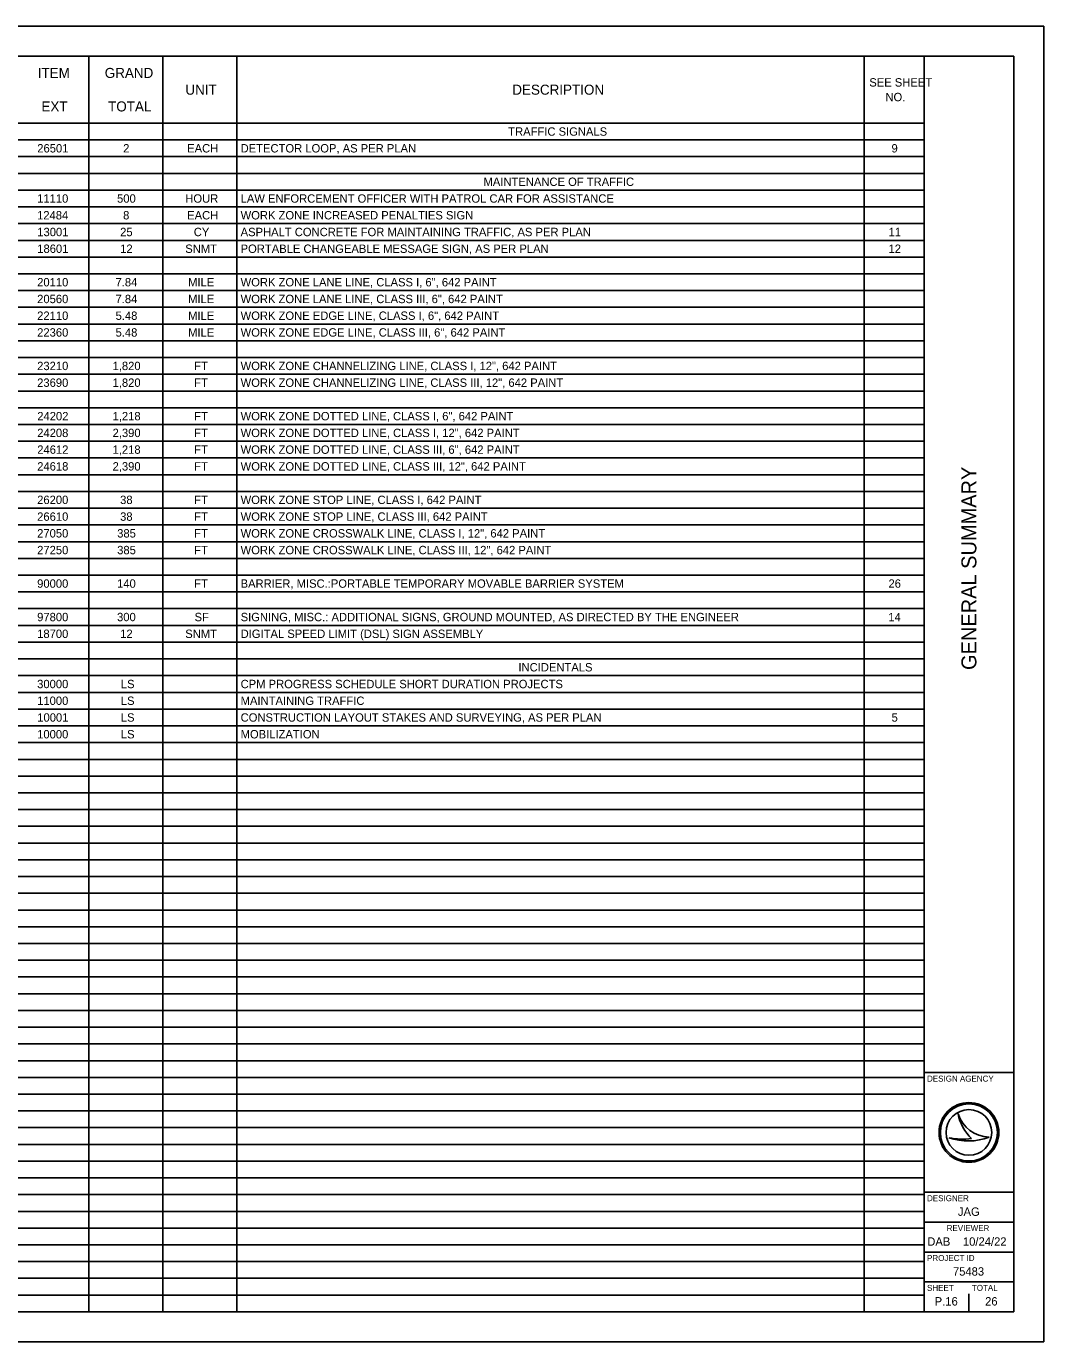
# Model space of a CAD drawing. Extents: x -32.2 to 34, y 0 to 22.
# Drawn here: x 16.99 to 34, y 0 to 22 of the extents above; entities that cross this region are included whole.
import ezdxf

# ---------------------------------------------------------------- set-up
doc = ezdxf.new("R2010")
doc.units = 0
for name, color, linetype in [('SH_Border', 7, 'Continuous'), ('SH_Cut_Line', 7, 'Continuous'), ('SH_Data', 7, 'Continuous'), ('SH_Text', 7, 'Continuous')]:
    doc.layers.add(name, color=color, linetype=linetype)

msp = doc.modelspace()

# ---------------------------------------------------------------- linework, layer by layer
at = {"layer": 'SH_Border'}
for p, q in [((32, 0.5), (32, 21.5)), ((32, 4.5), (33.5, 4.5)), ((32, 2.5), (33.5, 2.5)), ((32, 2), (33.5, 2)), ((32, 1.5), (33.5, 1.5)), ((32, 1), (33.5, 1))]:
    msp.add_line(p, q, dxfattribs=at)
msp.add_lwpolyline([(1.5, 21.5), (33.5, 21.5), (33.5, 0.5), (1.5, 0.5)], close=True, dxfattribs=at)
at = {"layer": 'SH_Cut_Line'}
msp.add_lwpolyline([(0, 0), (34, 0), (34, 22), (0, 22)], close=True, dxfattribs=at)
at = {"layer": 'SH_Data'}
for p, q in [((32.567, 3.81), (32.567, 3.81)), ((32.417, 3.41), (32.417, 3.41)), ((32.75, 3.5), (32.75, 3.5)), ((33.087, 3.419), (33.087, 3.419)), ((32.375, 0.675), (32.375, 0.675)), ((32.75, 0.5), (32.75, 0.8))]:
    msp.add_line(p, q, dxfattribs=at)
for radius in [0.5, 0.477, 0.477, 0.382]:
    msp.add_circle((32.75, 3.5), radius, dxfattribs=at)
for centre, radius, start, end in [((33.116, 3.998), 0.58, 198.9257, 198.9319), ((33.347, 3.97), 0.796, 191.6379, 191.6421), ((33.116, 3.998), 0.58, 198.9319, 267.1657), ((33.347, 3.97), 0.796, 191.6421, 226.0947), ((32.739, 4.37), 1.013, 251.4576, 290.0832), ((32.648, 4.654), 1.266, 259.4964, 259.4995), ((32.739, 4.37), 1.013, 251.4527, 251.4576), ((32.648, 4.654), 1.266, 259.4995, 276.6672)]:
    msp.add_arc(centre, radius, start, end, dxfattribs=at)
at = {"layer": 'SH_Text'}
for p, q in [((1.5, 21.5), (32.004, 21.5)), ((18.036, 21.5), (18.036, 0.5)), ((19.272, 21.5), (19.272, 0.5)), ((20.507, 21.5), (20.507, 0.5)), ((30.999, 21.5), (30.999, 0.5)), ((32.004, 21.5), (32.004, 0.5)), ((1.5, 20.38), (32.004, 20.38)), ((1.5, 20.1), (32.004, 20.1)), ((1.5, 19.82), (32.004, 19.82)), ((1.5, 19.54), (32.004, 19.54)), ((1.5, 19.26), (32.004, 19.26)), ((1.5, 18.98), (32.004, 18.98)), ((1.5, 18.7), (32.004, 18.7)), ((1.5, 18.42), (32.004, 18.42)), ((1.5, 18.14), (32.004, 18.14)), ((1.5, 17.86), (32.004, 17.86)), ((1.5, 17.58), (32.004, 17.58)), ((1.5, 17.3), (32.004, 17.3)), ((1.5, 17.02), (32.004, 17.02)), ((1.5, 16.74), (32.004, 16.74)), ((1.5, 16.46), (32.004, 16.46)), ((1.5, 16.18), (32.004, 16.18)), ((1.5, 15.9), (32.004, 15.9)), ((1.5, 15.62), (32.004, 15.62)), ((1.5, 15.34), (32.004, 15.34)), ((1.5, 15.06), (32.004, 15.06)), ((1.5, 14.78), (32.004, 14.78)), ((1.5, 14.5), (32.004, 14.5)), ((1.5, 14.22), (32.004, 14.22)), ((1.5, 13.94), (32.004, 13.94)), ((1.5, 13.66), (32.004, 13.66)), ((1.5, 13.38), (32.004, 13.38)), ((1.5, 13.1), (32.004, 13.1)), ((1.5, 12.82), (32.004, 12.82)), ((1.5, 12.54), (32.004, 12.54)), ((1.5, 12.26), (32.004, 12.26)), ((1.5, 11.98), (32.004, 11.98)), ((1.5, 11.7), (32.004, 11.7)), ((1.5, 11.42), (32.004, 11.42)), ((1.5, 11.14), (32.004, 11.14)), ((1.5, 10.86), (32.004, 10.86)), ((1.5, 10.58), (32.004, 10.58)), ((1.5, 10.3), (32.004, 10.3)), ((1.5, 10.02), (32.004, 10.02)), ((1.5, 9.74), (32.004, 9.74)), ((1.5, 9.46), (32.004, 9.46)), ((1.5, 9.18), (32.004, 9.18)), ((1.5, 8.9), (32.004, 8.9)), ((1.5, 8.62), (32.004, 8.62)), ((1.5, 8.34), (32.004, 8.34)), ((1.5, 8.06), (32.004, 8.06)), ((1.5, 7.78), (32.004, 7.78)), ((1.5, 7.5), (32.004, 7.5)), ((1.5, 7.22), (32.004, 7.22)), ((1.5, 6.94), (32.004, 6.94)), ((1.5, 6.66), (32.004, 6.66)), ((1.5, 6.38), (32.004, 6.38)), ((1.5, 6.1), (32.004, 6.1)), ((1.5, 5.82), (32.004, 5.82)), ((1.5, 5.54), (32.004, 5.54)), ((1.5, 5.26), (32.004, 5.26)), ((1.5, 4.98), (32.004, 4.98)), ((1.5, 4.7), (32.004, 4.7)), ((1.5, 4.42), (32.004, 4.42)), ((1.5, 4.14), (32.004, 4.14)), ((1.5, 3.86), (32.004, 3.86)), ((1.5, 3.58), (32.004, 3.58)), ((1.5, 3.3), (32.004, 3.3)), ((1.5, 3.02), (32.004, 3.02)), ((1.5, 2.74), (32.004, 2.74)), ((1.5, 2.46), (32.004, 2.46)), ((1.5, 2.18), (32.004, 2.18)), ((1.5, 1.9), (32.004, 1.9)), ((1.5, 1.62), (32.004, 1.62)), ((1.5, 1.34), (32.004, 1.34)), ((1.5, 1.06), (32.004, 1.06)), ((1.5, 0.78), (32.004, 0.78)), ((1.5, 0.5), (32.004, 0.5))]:
    msp.add_line(p, q, dxfattribs=at)

# ---------------------------------------------------------------- texts
at = {"layer": 'SH_Data'}
msp.add_text('GENERAL SUMMARY', height=0.25, rotation=90, dxfattribs=at).set_placement((32.875, 11.235))
for s, height, p in [('DESIGN AGENCY', 0.1, (32.05, 4.35)), ('DESIGNER', 0.1, (32.05, 2.35)), ('JAG', 0.14, (32.566, 2.105)), ('REVIEWER', 0.1, (32.378, 1.85)), ('DAB', 0.14, (32.054, 1.605)), ('10/24/22', 0.14, (32.65, 1.605)), ('PROJECT ID', 0.1, (32.05, 1.35)), ('75483', 0.14, (32.483, 1.105)), ('SHEET', 0.1, (32.05, 0.85)), ('TOTAL', 0.1, (32.8, 0.85)), ('P.16', 0.14, (32.178, 0.605)), ('26', 0.14, (33.021, 0.605))]:
    msp.add_text(s, height=height, dxfattribs=at).set_placement(p)
at = {"layer": 'SH_Text'}
for s, height, p in [('ITEM', 0.168, (17.181, 21.136)), ('GRAND', 0.168, (18.301, 21.136)), ('SEE SHEET ', 0.14, (31.084, 20.992)), ('UNIT', 0.168, (19.649, 20.856)), ('DESCRIPTION', 0.168, (25.115, 20.856)), ('EXT', 0.168, (17.242, 20.576)), ('TOTAL', 0.168, (18.357, 20.576)), ('NO.', 0.14, (31.354, 20.747)), ('TRAFFIC SIGNALS', 0.14, (25.047, 20.17)), ('26501', 0.14, (17.173, 19.89)), ('2', 0.14, (18.609, 19.89)), ('EACH', 0.14, (19.679, 19.89)), ('DETECTOR LOOP, AS PER PLAN', 0.14, (20.573, 19.89)), ('9', 0.14, (31.456, 19.89)), ('MAINTENANCE OF TRAFFIC', 0.14, (24.634, 19.33)), ('11110', 0.14, (17.171, 19.05)), ('500', 0.14, (18.507, 19.05)), ('HOUR', 0.14, (19.648, 19.05)), ('LAW ENFORCEMENT OFFICER WITH PATROL CAR FOR ASSISTANCE', 0.14, (20.573, 19.05)), ('12484', 0.14, (17.17, 18.77)), ('8', 0.14, (18.608, 18.77)), ('EACH', 0.14, (19.679, 18.77)), ('WORK ZONE INCREASED PENALTIES SIGN', 0.14, (20.573, 18.77)), ('13001', 0.14, (17.173, 18.49)), ('25', 0.14, (18.559, 18.49)), ('CY', 0.14, (19.79, 18.49)), ('ASPHALT CONCRETE FOR MAINTAINING TRAFFIC, AS PER PLAN', 0.14, (20.573, 18.49)), ('11', 0.14, (31.406, 18.49)), ('18601', 0.14, (17.173, 18.21)), ('12', 0.14, (18.559, 18.21)), ('SNMT', 0.14, (19.647, 18.21)), ('PORTABLE CHANGEABLE MESSAGE SIGN, AS PER PLAN', 0.14, (20.573, 18.21)), ('12', 0.14, (31.406, 18.21)), ('20110', 0.14, (17.171, 17.65)), ('7.84', 0.14, (18.481, 17.65)), ('MILE', 0.14, (19.695, 17.65)), ('WORK ZONE LANE LINE, CLASS I, 6", 642 PAINT', 0.14, (20.573, 17.65)), ('20560', 0.14, (17.171, 17.37)), ('7.84', 0.14, (18.481, 17.37)), ('MILE', 0.14, (19.695, 17.37)), ('WORK ZONE LANE LINE, CLASS III, 6", 642 PAINT', 0.14, (20.573, 17.37)), ('22110', 0.14, (17.171, 17.09)), ('5.48', 0.14, (18.482, 17.09)), ('MILE', 0.14, (19.695, 17.09)), ('WORK ZONE EDGE LINE, CLASS I, 6", 642 PAINT', 0.14, (20.573, 17.09)), ('22360', 0.14, (17.171, 16.81)), ('5.48', 0.14, (18.482, 16.81)), ('MILE', 0.14, (19.695, 16.81)), ('WORK ZONE EDGE LINE, CLASS III, 6", 642 PAINT', 0.14, (20.573, 16.81)), ('23210', 0.14, (17.171, 16.25)), ('1,820', 0.14, (18.432, 16.25)), ('FT', 0.14, (19.796, 16.25)), ('WORK ZONE CHANNELIZING LINE, CLASS I, 12", 642 PAINT', 0.14, (20.573, 16.25)), ('23690', 0.14, (17.171, 15.97)), ('1,820', 0.14, (18.432, 15.97)), ('FT', 0.14, (19.796, 15.97)), ('WORK ZONE CHANNELIZING LINE, CLASS III, 12", 642 PAINT', 0.14, (20.573, 15.97)), ('24202', 0.14, (17.173, 15.41)), ('1,218', 0.14, (18.432, 15.41)), ('FT', 0.14, (19.796, 15.41)), ('WORK ZONE DOTTED LINE, CLASS I, 6", 642 PAINT', 0.14, (20.573, 15.41)), ('24208', 0.14, (17.172, 15.13)), ('2,390', 0.14, (18.432, 15.13)), ('FT', 0.14, (19.796, 15.13)), ('WORK ZONE DOTTED LINE, CLASS I, 12", 642 PAINT', 0.14, (20.573, 15.13)), ('24612', 0.14, (17.173, 14.85)), ('1,218', 0.14, (18.432, 14.85)), ('FT', 0.14, (19.796, 14.85)), ('WORK ZONE DOTTED LINE, CLASS III, 6", 642 PAINT', 0.14, (20.573, 14.85)), ('24618', 0.14, (17.172, 14.57)), ('2,390', 0.14, (18.432, 14.57)), ('FT', 0.14, (19.796, 14.57)), ('WORK ZONE DOTTED LINE, CLASS III, 12", 642 PAINT', 0.14, (20.573, 14.57)), ('26200', 0.14, (17.171, 14.01)), ('38', 0.14, (18.558, 14.01)), ('FT', 0.14, (19.796, 14.01)), ('WORK ZONE STOP LINE, CLASS I, 642 PAINT', 0.14, (20.573, 14.01)), ('26610', 0.14, (17.171, 13.73)), ('38', 0.14, (18.558, 13.73)), ('FT', 0.14, (19.796, 13.73)), ('WORK ZONE STOP LINE, CLASS III, 642 PAINT', 0.14, (20.573, 13.73)), ('27050', 0.14, (17.171, 13.45)), ('385', 0.14, (18.509, 13.45)), ('FT', 0.14, (19.796, 13.45)), ('WORK ZONE CROSSWALK LINE, CLASS I, 12", 642 PAINT', 0.14, (20.573, 13.45)), ('27250', 0.14, (17.171, 13.17)), ('385', 0.14, (18.509, 13.17)), ('FT', 0.14, (19.796, 13.17)), ('WORK ZONE CROSSWALK LINE, CLASS III, 12", 642 PAINT', 0.14, (20.573, 13.17)), ('90000', 0.14, (17.171, 12.61)), ('140', 0.14, (18.507, 12.61)), ('FT', 0.14, (19.796, 12.61)), ('BARRIER, MISC.:PORTABLE TEMPORARY MOVABLE BARRIER SYSTEM', 0.14, (20.573, 12.61)), ('26', 0.14, (31.405, 12.61)), ('97800', 0.14, (17.171, 12.05)), ('300', 0.14, (18.507, 12.05)), ('SF', 0.14, (19.803, 12.05)), ('SIGNING, MISC.: ADDITIONAL SIGNS, GROUND MOUNTED, AS DIRECTED BY THE ENGINEER', 0.14, (20.573, 12.05)), ('14', 0.14, (31.403, 12.05)), ('18700', 0.14, (17.171, 11.77)), ('12', 0.14, (18.559, 11.77)), ('SNMT', 0.14, (19.647, 11.77)), ('DIGITAL SPEED LIMIT (DSL) SIGN ASSEMBLY', 0.14, (20.573, 11.77)), ('INCIDENTALS', 0.14, (25.218, 11.21)), ('30000', 0.14, (17.171, 10.93)), ('LS', 0.14, (18.57, 10.93)), ('CPM PROGRESS SCHEDULE SHORT DURATION PROJECTS', 0.14, (20.573, 10.93)), ('11000', 0.14, (17.171, 10.65)), ('LS', 0.14, (18.57, 10.65)), ('MAINTAINING TRAFFIC', 0.14, (20.573, 10.65)), ('10001', 0.14, (17.173, 10.37)), ('LS', 0.14, (18.57, 10.37)), ('CONSTRUCTION LAYOUT STAKES AND SURVEYING, AS PER PLAN', 0.14, (20.573, 10.37)), ('5', 0.14, (31.457, 10.37)), ('10000', 0.14, (17.171, 10.09)), ('LS', 0.14, (18.57, 10.09)), ('MOBILIZATION', 0.14, (20.573, 10.09))]:
    msp.add_text(s, height=height, dxfattribs=at).set_placement(p)

doc.saveas('drawing.dxf')
